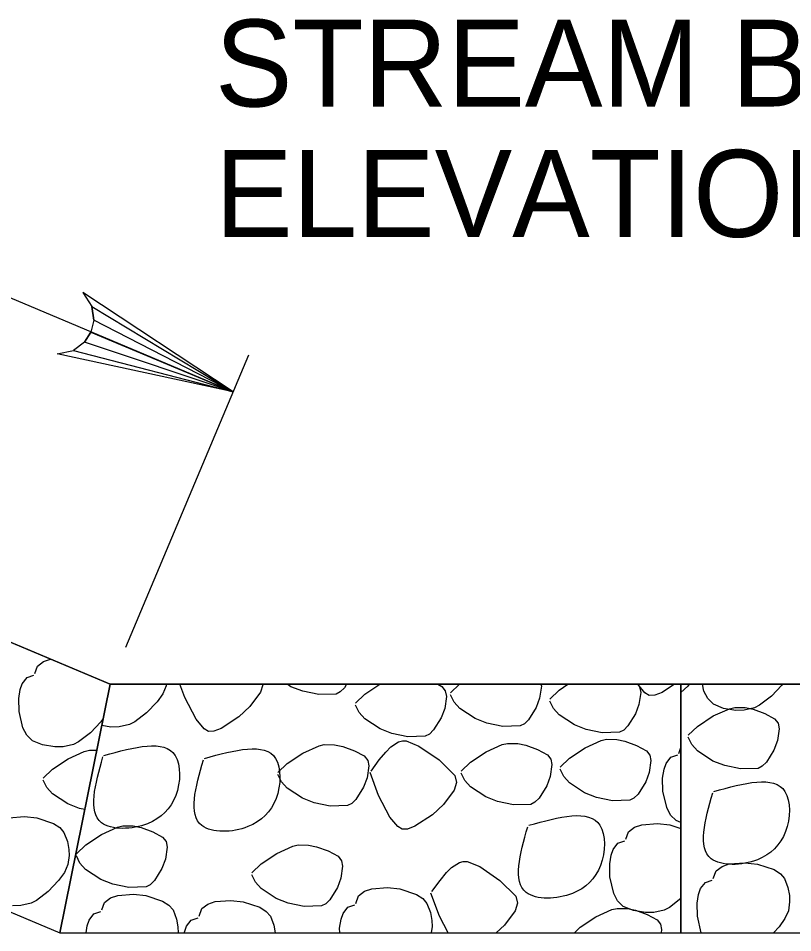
# Model space of a CAD drawing. Extents: x 3 to 3592, y -602 to 1171.
# Drawn here: x 137.89 to 169.08, y 901.74 to 938.56 of the extents above; entities that cross this region are included whole.
import ezdxf

# ---------------------------------------------------------------- set-up
doc = ezdxf.new("R2010")
doc.units = 0
doc.layers.add('2', color=7, linetype='Continuous')
doc.layers.add('3', color=7, linetype='Continuous')

msp = doc.modelspace()

# ---------------------------------------------------------------- linework, layer by layer
at = {"layer": '2'}
for p, q in [((146.55, 923.515), (131.449, 929.873)), ((142.224, 913.241), (147.181, 925.013)), ((141.594, 911.743), (139.574, 901.743)), ((164.574, 901.743), (164.574, 911.743))]:
    msp.add_line(p, q, dxfattribs=at)
for points in [[(78.674, 938.235), (141.594, 911.743), (187.555, 911.743), (250.474, 938.235)], [(146.55, 923.515), (139.46, 925.05), (140.114, 925.188), (146.55, 923.515), (140.561, 925.518), (140.822, 925.927), (146.55, 923.515), (140.932, 926.4), (140.856, 926.95), (146.55, 923.515), (140.497, 927.514), (140.856, 926.95), (140.932, 926.4), (140.822, 925.927), (140.561, 925.518), (140.114, 925.188)], [(92.074, 921.743), (139.574, 901.743), (189.574, 901.743), (237.074, 921.743)], [(138.674, 912.478), (138.916, 912.66)], [(138.916, 912.66), (139.194, 912.754)], [(138.564, 912.173), (138.674, 912.478)], [(138.057, 911.765), (138.247, 912.015)], [(138.247, 912.015), (138.524, 912.112)], [(137.974, 911.536), (138.057, 911.765)], [(141.584, 911.747), (141.589, 911.72)], [(143.855, 911.677), (143.718, 911.36)], [(143.865, 911.743), (143.855, 911.677)], [(144.601, 911.208), (144.403, 911.743)], [(147.745, 911.725), (147.649, 911.422)], [(147.741, 911.743), (147.745, 911.725)], [(148.874, 911.648), (148.728, 911.743)], [(149.352, 911.465), (148.874, 911.648)], [(151.028, 911.603), (150.86, 911.438)], [(151.115, 911.743), (151.028, 911.603)], [(151.853, 911.346), (152.452, 911.743)], [(154.784, 911.743), (154.951, 911.653)], [(154.951, 911.653), (155.091, 911.475)], [(155.301, 911.4), (155.659, 911.743)], [(158.958, 911.665), (158.888, 911.185)], [(158.943, 911.743), (158.958, 911.665)], [(159.677, 911.509), (160.031, 911.743)], [(162.832, 911.743), (162.915, 911.638)], [(163.124, 911.401), (162.841, 911.743)], [(162.915, 911.638), (162.958, 911.414)], [(164.318, 911.743), (163.819, 911.415)], [(164.863, 911.674), (164.574, 911.409)], [(164.914, 911.743), (164.863, 911.674)], [(165.506, 911.467), (165.441, 911.743)], [(168.639, 911.709), (168.22, 911.269)], [(168.664, 911.743), (168.639, 911.709)], [(137.917, 911.178), (137.974, 911.536)], [(137.927, 910.654), (137.917, 911.178)], [(143.718, 911.36), (143.482, 911.037)], [(145.055, 910.34), (144.601, 911.208)], [(147.649, 911.422), (147.221, 910.844)], [(149.993, 911.33), (149.352, 911.465)], [(150.694, 911.351), (149.993, 911.33)], [(150.86, 911.438), (150.694, 911.351)], [(151.477, 910.986), (151.853, 911.346)], [(155.134, 911.252), (155.065, 910.772)], [(155.091, 911.475), (155.134, 911.252)], [(155.446, 911.025), (155.301, 911.319)], [(158.888, 911.185), (158.745, 910.806)], [(159.301, 911.149), (159.677, 911.509)], [(162.958, 911.414), (162.889, 910.934)], [(163.301, 911.296), (163.124, 911.401)], [(163.521, 911.301), (163.301, 911.296)], [(163.819, 911.415), (163.521, 911.301)], [(165.659, 911.166), (165.506, 911.467)], [(168.22, 911.269), (167.744, 910.902)], [(143.482, 911.037), (143.063, 910.596)], [(147.221, 910.844), (146.772, 910.43)], [(151.623, 910.611), (151.477, 910.906)], [(155.671, 910.767), (155.446, 911.025)], [(158.745, 910.806), (158.442, 910.319)], [(159.447, 910.774), (159.301, 911.068)], [(162.889, 910.934), (162.746, 910.555)], [(165.886, 910.942), (165.659, 911.166)], [(166.297, 910.776), (165.886, 910.942)], [(166.532, 910.762), (166.746, 910.815)], [(166.746, 910.815), (167.161, 910.811)], [(167.161, 910.811), (167.487, 910.743)], [(167.744, 910.902), (167.537, 910.796)], [(138.082, 909.992), (137.927, 910.654)], [(143.063, 910.596), (142.587, 910.229)], [(151.848, 910.354), (151.623, 910.611)], [(155.065, 910.772), (154.921, 910.393)], [(156.287, 910.364), (155.671, 910.767)], [(159.672, 910.516), (159.447, 910.774)], [(160.288, 910.113), (159.672, 910.516)], [(162.746, 910.555), (162.443, 910.068)], [(165.252, 910.051), (165.882, 910.468)], [(165.882, 910.468), (166.532, 910.762)], [(166.785, 910.695), (166.297, 910.776)], [(167.119, 910.701), (166.785, 910.695)], [(167.537, 910.796), (167.119, 910.701)], [(167.487, 910.743), (167.956, 910.572)], [(167.956, 910.572), (168.35, 910.358)], [(141.215, 910.234), (140.797, 909.794)], [(141.317, 910.373), (141.215, 910.234)], [(141.627, 910.022), (141.259, 910.083)], [(142.38, 910.123), (141.962, 910.028)], [(142.587, 910.229), (142.38, 910.123)], [(145.374, 909.954), (145.055, 910.34)], [(146.772, 910.43), (146.069, 909.968)], [(152.464, 909.95), (151.848, 910.354)], [(154.921, 910.393), (154.619, 909.905)], [(156.766, 910.18), (156.287, 910.364)], [(157.407, 910.045), (156.766, 910.18)], [(158.108, 910.067), (157.407, 910.045)], [(158.274, 910.154), (158.108, 910.067)], [(158.442, 910.319), (158.274, 910.154)], [(160.767, 909.929), (160.288, 910.113)], [(162.443, 910.068), (162.274, 909.903)], [(168.35, 910.358), (168.49, 910.18)], [(168.49, 910.18), (168.533, 909.957)], [(138.236, 909.691), (138.082, 909.992)], [(140.797, 909.794), (140.321, 909.426)], [(141.962, 910.028), (141.627, 910.022)], [(145.551, 909.849), (145.374, 909.954)], [(145.771, 909.855), (145.551, 909.849)], [(146.069, 909.968), (145.771, 909.855)], [(152.943, 909.767), (152.464, 909.95)], [(153.583, 909.632), (152.943, 909.767)], [(154.45, 909.74), (154.284, 909.653)], [(154.619, 909.905), (154.45, 909.74)], [(161.407, 909.794), (160.767, 909.929)], [(162.109, 909.816), (161.407, 909.794)], [(162.274, 909.903), (162.109, 909.816)], [(164.876, 909.691), (165.252, 910.051)], [(168.533, 909.957), (168.464, 909.477)], [(138.463, 909.467), (138.236, 909.691)], [(138.874, 909.301), (138.463, 909.467)], [(140.321, 909.426), (140.113, 909.321)], [(152.894, 909.221), (153.205, 909.428)], [(153.205, 909.428), (153.36, 909.471)], [(153.36, 909.471), (153.513, 909.465)], [(153.513, 909.465), (154.023, 909.26)], [(154.284, 909.653), (153.583, 909.632)], [(157.385, 909.314), (157.598, 909.367)], [(157.598, 909.367), (158.014, 909.363)], [(158.014, 909.363), (158.339, 909.295)], [(160.72, 909.183), (161.371, 909.476)], [(161.371, 909.476), (161.584, 909.529)], [(161.584, 909.529), (162, 909.525)], [(162, 909.525), (162.325, 909.458)], [(162.325, 909.458), (162.794, 909.286)], [(165.022, 909.316), (164.876, 909.611)], [(168.464, 909.477), (168.321, 909.098)], [(139.361, 909.22), (138.874, 909.301)], [(139.696, 909.226), (139.361, 909.22)], [(140.113, 909.321), (139.696, 909.226)], [(139.903, 908.746), (140.554, 909.04)], [(140.554, 909.04), (140.767, 909.093)], [(140.767, 909.093), (141.058, 909.09)], [(148.726, 908.551), (149.355, 908.968)], [(149.355, 908.968), (150.006, 909.262)], [(150.006, 909.262), (150.219, 909.315)], [(150.219, 909.315), (150.635, 909.311)], [(150.635, 909.311), (150.96, 909.243)], [(150.96, 909.243), (151.43, 909.072)], [(151.43, 909.072), (151.824, 908.858)], [(152.425, 908.697), (152.689, 909.016)], [(152.689, 909.016), (152.894, 909.221)], [(154.023, 909.26), (154.84, 908.7)], [(156.105, 908.603), (156.734, 909.02)], [(156.734, 909.02), (157.385, 909.314)], [(158.339, 909.295), (158.808, 909.124)], [(158.808, 909.124), (159.203, 908.91)], [(160.091, 908.766), (160.72, 909.183)], [(162.794, 909.286), (163.189, 909.072)], [(163.189, 909.072), (163.329, 908.895)], [(164.489, 908.963), (164.574, 909.2)], [(165.247, 909.059), (165.022, 909.316)], [(165.863, 908.655), (165.247, 909.059)], [(168.321, 909.098), (168.018, 908.61)], [(139.274, 908.329), (139.903, 908.746)], [(151.824, 908.858), (151.964, 908.68)], [(151.964, 908.68), (152.007, 908.457)], [(152.099, 908.253), (152.425, 908.697)], [(154.84, 908.7), (155.472, 908.071)], [(155.729, 908.243), (156.105, 908.603)], [(159.203, 908.91), (159.343, 908.732)], [(159.343, 908.732), (159.386, 908.509)], [(159.715, 908.406), (160.091, 908.766)], [(163.372, 908.671), (163.303, 908.191)], [(163.329, 908.895), (163.372, 908.671)], [(163.981, 908.555), (164.172, 908.805)], [(164.172, 908.805), (164.448, 908.902)], [(166.342, 908.472), (165.863, 908.655)], [(168.018, 908.61), (167.849, 908.445)], [(138.898, 907.969), (139.274, 908.329)], [(148.35, 908.191), (148.726, 908.551)], [(152.007, 908.457), (151.938, 907.977)], [(159.386, 908.509), (159.317, 908.029)], [(159.861, 908.031), (159.715, 908.325)], [(163.841, 907.967), (163.899, 908.326)], [(163.899, 908.326), (163.981, 908.555)], [(166.982, 908.337), (166.342, 908.472)], [(167.683, 908.358), (166.982, 908.337)], [(167.849, 908.445), (167.683, 908.358)], [(139.044, 907.595), (138.898, 907.889)], [(148.496, 907.816), (148.35, 908.111)], [(151.938, 907.977), (151.794, 907.598)], [(152.401, 907.269), (152.059, 908.192)], [(155.472, 908.071), (155.545, 907.786)], [(155.875, 907.868), (155.729, 908.163)], [(156.099, 907.611), (155.875, 907.868)], [(159.317, 908.029), (159.173, 907.65)], [(160.085, 907.773), (159.861, 908.031)], [(163.303, 908.191), (163.159, 907.812)], [(163.852, 907.444), (163.841, 907.967)], [(139.268, 907.337), (139.044, 907.595)], [(148.72, 907.559), (148.496, 907.816)], [(149.337, 907.155), (148.72, 907.559)], [(151.794, 907.598), (151.492, 907.11)], [(155.545, 907.786), (155.449, 907.484)], [(156.716, 907.207), (156.099, 907.611)], [(159.173, 907.65), (158.87, 907.162)], [(160.702, 907.37), (160.085, 907.773)], [(163.159, 907.812), (162.856, 907.325)], [(139.885, 906.933), (139.268, 907.337)], [(149.816, 906.972), (149.337, 907.155)], [(152.855, 906.401), (152.401, 907.269)], [(155.449, 907.484), (155.021, 906.905)], [(157.194, 907.024), (156.716, 907.207)], [(158.87, 907.162), (158.702, 906.997)], [(161.18, 907.186), (160.702, 907.37)], [(161.821, 907.051), (161.18, 907.186)], [(162.688, 907.16), (162.522, 907.073)], [(162.856, 907.325), (162.688, 907.16)], [(164.007, 906.782), (163.852, 907.444)], [(140.364, 906.75), (139.885, 906.933)], [(150.456, 906.837), (149.816, 906.972)], [(151.157, 906.858), (150.456, 906.837)], [(151.323, 906.945), (151.157, 906.858)], [(151.492, 907.11), (151.323, 906.945)], [(155.021, 906.905), (154.572, 906.492)], [(157.835, 906.889), (157.194, 907.024)], [(158.536, 906.91), (157.835, 906.889)], [(158.702, 906.997), (158.536, 906.91)], [(162.522, 907.073), (161.821, 907.051)], [(164.16, 906.481), (164.007, 906.782)], [(137.513, 906.37), (138.141, 906.42)], [(138.141, 906.42), (138.643, 906.362)], [(140.576, 906.705), (140.364, 906.75)], [(153.174, 906.016), (152.855, 906.401)], [(154.572, 906.492), (153.869, 906.03)], [(164.388, 906.257), (164.16, 906.481)], [(138.643, 906.362), (139.315, 906.141)], [(139.315, 906.141), (139.568, 905.978)], [(141.89, 905.992), (142.104, 906.046)], [(142.104, 906.046), (142.519, 906.041)], [(142.519, 906.041), (142.845, 905.974)], [(153.351, 905.91), (153.174, 906.016)], [(153.869, 906.03), (153.571, 905.916)], [(162.708, 905.993), (163.003, 906.092)], [(163.003, 906.092), (163.631, 906.142)], [(163.631, 906.142), (164.132, 906.084)], [(164.132, 906.084), (164.574, 905.939)], [(164.574, 906.181), (164.388, 906.257)], [(139.568, 905.978), (139.734, 905.783)], [(139.734, 905.783), (139.876, 905.418)], [(140.61, 905.282), (141.24, 905.699)], [(141.24, 905.699), (141.89, 905.992)], [(142.845, 905.974), (143.314, 905.803)], [(143.314, 905.803), (143.708, 905.588)], [(153.571, 905.916), (153.351, 905.91)], [(162.356, 905.505), (162.466, 905.81)], [(162.466, 905.81), (162.708, 905.993)], [(139.876, 905.418), (139.933, 905.098)], [(140.234, 904.922), (140.61, 905.282)], [(143.708, 905.588), (143.849, 905.411)], [(143.849, 905.411), (143.892, 905.188)], [(161.849, 905.098), (162.039, 905.347)], [(162.039, 905.347), (162.316, 905.445)], [(139.933, 905.098), (139.941, 904.849)], [(143.892, 905.188), (143.822, 904.708)], [(147.675, 904.514), (148.305, 904.931)], [(148.305, 904.931), (148.955, 905.225)], [(148.955, 905.225), (149.169, 905.278)], [(149.169, 905.278), (149.584, 905.274)], [(149.584, 905.274), (149.91, 905.206)], [(149.91, 905.206), (150.379, 905.035)], [(150.379, 905.035), (150.773, 904.821)], [(161.766, 904.869), (161.849, 905.098)], [(139.941, 904.849), (139.891, 904.486)], [(140.38, 904.547), (140.234, 904.841)], [(140.605, 904.289), (140.38, 904.547)], [(143.822, 904.708), (143.679, 904.329)], [(150.773, 904.821), (150.914, 904.643)], [(150.914, 904.643), (150.957, 904.42)], [(155.346, 904.365), (155.657, 904.573)], [(155.657, 904.573), (155.812, 904.616)], [(155.812, 904.616), (155.965, 904.609)], [(155.965, 904.609), (156.476, 904.404)], [(161.709, 904.51), (161.766, 904.869)], [(166.527, 904.511), (167.156, 904.561)], [(167.156, 904.561), (167.657, 904.503)], [(139.891, 904.486), (139.754, 904.168)], [(141.221, 903.886), (140.605, 904.289)], [(143.679, 904.329), (143.376, 903.841)], [(147.299, 904.154), (147.675, 904.514)], [(150.957, 904.42), (150.887, 903.94)], [(155.141, 904.161), (155.346, 904.365)], [(156.476, 904.404), (157.292, 903.844)], [(161.719, 903.987), (161.709, 904.51)], [(165.881, 903.925), (165.991, 904.23)], [(165.991, 904.23), (166.233, 904.412)], [(166.233, 904.412), (166.527, 904.511)], [(167.657, 904.503), (168.33, 904.283)], [(168.33, 904.283), (168.582, 904.119)], [(139.518, 903.845), (139.099, 903.404)], [(139.754, 904.168), (139.518, 903.845)], [(141.7, 903.703), (141.221, 903.886)], [(143.376, 903.841), (143.208, 903.676)], [(147.445, 903.779), (147.299, 904.073)], [(150.887, 903.94), (150.744, 903.561)], [(154.551, 903.397), (154.877, 903.841)], [(154.877, 903.841), (155.141, 904.161)], [(157.292, 903.844), (157.924, 903.216)], [(161.874, 903.324), (161.719, 903.987)], [(165.564, 903.767), (165.84, 903.864)], [(168.582, 904.119), (168.748, 903.925)], [(168.748, 903.925), (168.89, 903.56)], [(142.341, 903.568), (141.7, 903.703)], [(143.042, 903.589), (142.341, 903.568)], [(143.208, 903.676), (143.042, 903.589)], [(147.67, 903.522), (147.445, 903.779)], [(148.286, 903.118), (147.67, 903.522)], [(150.744, 903.561), (150.441, 903.073)], [(151.835, 903.412), (152.129, 903.512)], [(152.129, 903.512), (152.757, 903.561)], [(152.757, 903.561), (153.259, 903.503)], [(153.259, 903.503), (153.932, 903.283)], [(165.291, 903.288), (165.373, 903.517)], [(165.373, 903.517), (165.564, 903.767)], [(168.89, 903.56), (168.947, 903.239)], [(139.099, 903.404), (138.623, 903.037)], [(141.368, 902.964), (141.611, 903.146)], [(141.611, 903.146), (141.905, 903.246)], [(141.905, 903.246), (142.533, 903.295)], [(142.533, 903.295), (143.035, 903.238)], [(143.035, 903.238), (143.708, 903.017)], [(148.765, 902.935), (148.286, 903.118)], [(150.441, 903.073), (150.273, 902.908)], [(151.483, 902.925), (151.593, 903.23)], [(151.593, 903.23), (151.835, 903.412)], [(153.932, 903.283), (154.184, 903.119)], [(154.184, 903.119), (154.35, 902.925)], [(154.854, 902.414), (154.511, 903.337)], [(157.924, 903.216), (157.998, 902.931)], [(162.028, 903.023), (161.874, 903.324)], [(164.574, 903.115), (164.113, 902.759)], [(165.233, 902.929), (165.291, 903.288)], [(168.947, 903.239), (168.956, 902.99)], [(137.998, 902.836), (137.663, 902.831)], [(138.416, 902.932), (137.998, 902.836)], [(138.623, 903.037), (138.416, 902.932)], [(141.258, 902.659), (141.368, 902.964)], [(143.708, 903.017), (143.96, 902.854)], [(143.96, 902.854), (144.126, 902.659)], [(145.179, 902.408), (145.289, 902.713)], [(145.289, 902.713), (145.531, 902.895)], [(145.531, 902.895), (145.826, 902.995)], [(145.826, 902.995), (146.454, 903.044)], [(146.454, 903.044), (146.955, 902.987)], [(146.955, 902.987), (147.628, 902.766)], [(147.628, 902.766), (147.88, 902.603)], [(149.406, 902.8), (148.765, 902.935)], [(150.107, 902.821), (149.406, 902.8)], [(150.273, 902.908), (150.107, 902.821)], [(150.975, 902.517), (151.166, 902.767)], [(151.166, 902.767), (151.442, 902.864)], [(154.35, 902.925), (154.492, 902.56)], [(157.998, 902.931), (157.902, 902.628)], [(161.799, 902.671), (162.012, 902.724)], [(162.012, 902.724), (162.428, 902.72)], [(162.255, 902.799), (162.028, 903.023)], [(162.666, 902.633), (162.255, 902.799)], [(162.428, 902.72), (162.753, 902.652)], [(164.113, 902.759), (163.905, 902.654)], [(165.244, 902.406), (165.233, 902.929)], [(168.956, 902.99), (168.906, 902.627)], [(140.751, 902.252), (140.942, 902.501)], [(140.942, 902.501), (141.218, 902.599)], [(144.126, 902.659), (144.268, 902.294)], [(144.862, 902.25), (145.138, 902.348)], [(147.88, 902.603), (148.047, 902.408)], [(148.047, 902.408), (148.188, 902.043)], [(150.893, 902.288), (150.975, 902.517)], [(154.492, 902.56), (154.549, 902.239)], [(155.204, 901.743), (154.854, 902.414)], [(157.902, 902.628), (157.474, 902.05)], [(160.519, 901.96), (161.148, 902.377)], [(161.148, 902.377), (161.799, 902.671)], [(163.153, 902.553), (162.666, 902.633)], [(162.753, 902.652), (163.222, 902.481)], [(163.488, 902.558), (163.153, 902.553)], [(163.222, 902.481), (163.617, 902.267)], [(163.905, 902.654), (163.488, 902.558)], [(165.399, 901.744), (165.244, 902.406)], [(168.906, 902.627), (168.769, 902.309)], [(140.624, 901.743), (140.669, 902.022)], [(140.669, 902.022), (140.751, 902.252)], [(144.268, 902.294), (144.325, 901.974)], [(144.325, 901.974), (144.333, 901.743)], [(144.589, 901.771), (144.672, 902.001)], [(144.672, 902.001), (144.862, 902.25)], [(148.188, 902.043), (148.242, 901.743)], [(150.835, 901.93), (150.893, 902.288)], [(154.558, 901.99), (154.523, 901.743)], [(154.549, 902.239), (154.558, 901.99)], [(157.474, 902.05), (157.14, 901.743)], [(163.617, 902.267), (163.757, 902.09)], [(163.757, 902.09), (163.8, 901.866)], [(168.532, 901.986), (168.301, 901.743)], [(168.769, 902.309), (168.532, 901.986)], [(144.585, 901.743), (144.589, 901.771)], [(150.839, 901.743), (150.835, 901.93)], [(160.292, 901.743), (160.519, 901.96)], [(163.8, 901.866), (163.782, 901.743)], [(165.4, 901.743), (165.399, 901.744)]]:
    msp.add_lwpolyline(points, dxfattribs=at)
for points in [[(141.594, 911.743), (119.705, 920.959), (115.824, 911.743), (139.574, 901.743)], [(164.574, 911.743), (141.594, 911.743), (139.574, 901.743), (164.574, 901.743)], [(187.555, 911.743), (164.574, 911.743), (164.574, 901.743), (189.574, 901.743)]]:
    msp.add_lwpolyline(points, close=True, dxfattribs=at)
for points in [[(141.346, 908.879), (144.213, 908.879), (144.234, 907.263), (143.103, 906.132), (141.245, 906.172), (141.305, 908.818)], [(145.387, 908.761), (148.255, 908.761), (148.275, 907.145), (147.144, 906.014), (145.286, 906.054), (145.347, 908.7)], [(165.9, 907.429), (168.768, 907.429), (168.788, 905.813), (167.657, 904.682), (165.799, 904.722), (165.86, 907.368)], [(158.451, 906.069), (161.318, 906.069), (161.339, 904.454), (160.208, 903.323), (158.35, 903.363), (158.41, 906.009)]]:
    msp.add_spline(points, degree=3, dxfattribs=at)

# ---------------------------------------------------------------- texts
at = {"layer": '3'}
for s, p in [('STREAM BED', (145.816, 935.006)), ('ELEVATION', (145.816, 929.756))]:
    msp.add_text(s, height=3.5, dxfattribs=at).set_placement(p)

doc.saveas('drawing.dxf')
